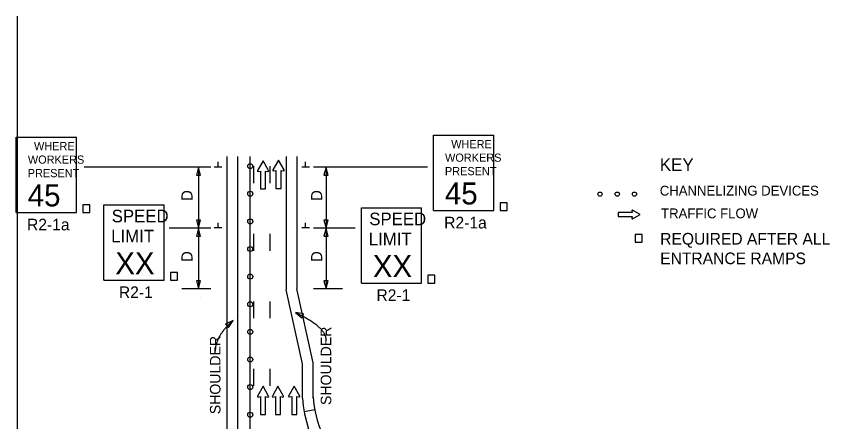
# Model space of a CAD drawing. Extents: x 16115 to 18454, y 4946 to 8326.
# Drawn here: x 16732 to 17380, y 7978 to 8301 of the extents above; entities that cross this region are included whole.
import ezdxf

# ---------------------------------------------------------------- set-up
doc = ezdxf.new("R2010")
doc.units = 0
for name, color, linetype in [('BORDER', 7, 'Continuous'), ('Level 10', 7, 'Continuous'), ('MT_SCRATCH_LEVEL_E', 7, 'Continuous'), ('PAVT_EDGE_EX', 7, 'Continuous'), ('SCRATCH_LEVEL_A', 7, 'Continuous'), ('TYPICAL_TEXT_DIMEN_EX', 7, 'Continuous')]:
    doc.layers.add(name, color=color, linetype=linetype)

msp = doc.modelspace()

# ---------------------------------------------------------------- linework, layer by layer
at = {"layer": 'BORDER'}
for p, q in [((16892.63, 8180.53), (16892.63, 8184.72)), ((16962.35, 8180.53), (16962.35, 8184.72)), ((16886.89, 8180.43), (16785.98, 8180.43)), ((16877.08, 8180.43), (16875.39, 8174.03)), ((16877.08, 8180.43), (16877.08, 8132)), ((16878.78, 8174.03), (16877.08, 8180.43)), ((16895.66, 8180.53), (16889.61, 8180.53)), ((16965.37, 8180.53), (16959.32, 8180.53)), ((17059.37, 8180.43), (16968.59, 8180.43)), ((16978.69, 8180.43), (16977, 8174.03)), ((16978.69, 8180.43), (16978.69, 8132)), ((16980.39, 8174.03), (16978.69, 8180.43)), ((16875.39, 8174.03), (16877.08, 8174.03)), ((16877.08, 8174.03), (16878.78, 8174.03)), ((16977, 8174.03), (16978.69, 8174.03)), ((16978.69, 8174.03), (16980.39, 8174.03)), ((16877.08, 8138.41), (16875.39, 8138.41)), ((16875.39, 8138.41), (16877.08, 8132)), ((16877.08, 8132), (16878.78, 8138.41)), ((16878.78, 8138.41), (16877.08, 8138.41)), ((16978.69, 8138.41), (16977, 8138.41)), ((16977, 8138.41), (16978.69, 8132)), ((16978.69, 8132), (16980.39, 8138.41)), ((16980.39, 8138.41), (16978.69, 8138.41)), ((16886.89, 8132), (16853.73, 8132)), ((16877.08, 8132), (16875.39, 8125.6)), ((16877.08, 8132), (16877.08, 8083.57)), ((16878.78, 8125.6), (16877.08, 8132)), ((16895.66, 8132.1), (16889.61, 8132.1)), ((16892.63, 8132.1), (16892.63, 8136.29)), ((16965.37, 8132.1), (16959.32, 8132.1)), ((16962.35, 8132.1), (16962.35, 8136.29)), ((17001.75, 8132), (16968.59, 8132)), ((16978.69, 8132), (16977, 8125.6)), ((16978.69, 8132), (16978.69, 8083.57)), ((16980.39, 8125.6), (16978.69, 8132)), ((16875.39, 8125.6), (16877.08, 8125.6)), ((16877.08, 8125.6), (16878.78, 8125.6)), ((16977, 8125.6), (16978.69, 8125.6)), ((16978.69, 8125.6), (16980.39, 8125.6)), ((16877.08, 8089.98), (16875.39, 8089.98)), ((16875.39, 8089.98), (16877.08, 8083.57)), ((16877.08, 8083.57), (16878.78, 8089.98)), ((16878.78, 8089.98), (16877.08, 8089.98)), ((16978.69, 8089.98), (16977, 8089.98)), ((16977, 8089.98), (16978.69, 8083.57)), ((16978.69, 8083.57), (16980.39, 8089.98)), ((16980.39, 8089.98), (16978.69, 8089.98)), ((16886.89, 8083.57), (16863.83, 8083.57)), ((16991.66, 8083.57), (16968.59, 8083.57)), ((16878.97, 8076.84), (16878.97, 8076.84)), ((16954.29, 8064.7), (16959.41, 8060.5)), ((16960.82, 8063.58), (16954.29, 8064.7)), ((16959.41, 8060.5), (16960.11, 8062.04)), ((16960.11, 8062.04), (16960.82, 8063.58)), ((16904.66, 8058.27), (16898.69, 8055.4)), ((16898.69, 8055.4), (16899.79, 8054.11)), ((16899.79, 8054.11), (16900.89, 8052.82)), ((16900.89, 8052.82), (16904.66, 8058.27)), ((16961.22, 7985.76), (16969.66, 7987.47))]:
    msp.add_line(p, q, dxfattribs=at)
msp.add_lwpolyline([(16918.32, 7255.33), (16918.32, 8189.12)], dxfattribs=at)
for centre in [(16918.32, 8181.33), (16918.32, 8159.33), (16918.32, 8137.33), (16918.32, 8115.33), (16918.32, 8093.33), (16918.32, 8071.33), (16918.32, 8049.33), (16918.32, 8027.33), (16918.32, 8005.33), (16918.32, 7983.33)]:
    msp.add_circle(centre, 2, dxfattribs=at)
for points in [[(16954.29, 8064.7), (16978.64, 8053.56), (16978.64, 8042.42)], [(16904.66, 8058.27), (16890.42, 8046.09), (16890.42, 8033.92)]]:
    msp.add_open_spline(points, degree=2, dxfattribs=at)
at = {"layer": 'Level 10'}
for p, q in [((16731.93, 8204.43), (16779.93, 8204.43)), ((16731.93, 8144.43), (16731.93, 8204.43)), ((16779.93, 8144.43), (16779.93, 8204.43)), ((17064.2, 8205.99), (17112.2, 8205.99)), ((17064.2, 8145.99), (17064.2, 8205.99)), ((17112.2, 8145.99), (17112.2, 8205.99)), ((16731.93, 8144.43), (16779.93, 8144.43)), ((16801.65, 8150.53), (16849.65, 8150.53)), ((16801.65, 8090.53), (16801.65, 8150.53)), ((16849.65, 8090.53), (16849.65, 8150.53)), ((17006.8, 8148.2), (17054.8, 8148.2)), ((17006.8, 8088.2), (17006.8, 8148.2)), ((17054.8, 8088.2), (17054.8, 8148.2)), ((17064.2, 8145.99), (17112.2, 8145.99)), ((16801.65, 8090.53), (16849.65, 8090.53)), ((17006.8, 8088.2), (17054.8, 8088.2))]:
    msp.add_line(p, q, dxfattribs=at)
for points in [[(17117.22, 8145.99), (17122.81, 8145.99), (17122.81, 8152.16), (17117.22, 8152.16)], [(16784.94, 8144.43), (16790.54, 8144.43), (16790.54, 8150.61), (16784.94, 8150.61)], [(17224.98, 8120.68), (17230.57, 8120.68), (17230.57, 8126.85), (17224.98, 8126.85)], [(16854.67, 8090.53), (16860.26, 8090.53), (16860.26, 8096.7), (16854.67, 8096.7)], [(17059.82, 8088.2), (17065.41, 8088.2), (17065.41, 8094.37), (17059.82, 8094.37)]]:
    msp.add_lwpolyline(points, close=True, dxfattribs=at)
for centre in [(17196.89, 8159.03), (17210.59, 8159.03), (17224.3, 8159.03)]:
    msp.add_circle(centre, 1.68, dxfattribs=at)
at = {"layer": 'MT_SCRATCH_LEVEL_E'}
for p, q in [((16928.48, 8185.61), (16924.06, 8177.81)), ((16932.94, 8177.81), (16928.48, 8185.61)), ((16940.76, 8186.06), (16936.34, 8178.27)), ((16945.22, 8178.27), (16940.76, 8186.06)), ((16924.58, 8177.08), (16926.49, 8177.42)), ((16926.49, 8177.42), (16926.49, 8163.15)), ((16930.52, 8163.15), (16930.52, 8177.42)), ((16930.52, 8177.42), (16932.43, 8177.08)), ((16936.85, 8177.53), (16938.77, 8177.87)), ((16938.77, 8177.87), (16938.77, 8163.6)), ((16942.79, 8163.6), (16942.79, 8177.87)), ((16942.79, 8177.87), (16944.71, 8177.53)), ((16926.49, 8163.15), (16930.52, 8163.15)), ((16938.77, 8163.6), (16942.79, 8163.6)), ((17222.53, 8144.36), (17211.38, 8144.36)), ((17211.38, 8144.36), (17211.38, 8141.22)), ((17222.53, 8144.36), (17211.38, 8144.36)), ((17211.38, 8144.36), (17211.38, 8141.22)), ((17222.26, 8145.86), (17222.53, 8144.36)), ((17222.26, 8145.86), (17222.53, 8144.36)), ((17228.93, 8142.8), (17222.84, 8146.26)), ((17228.93, 8142.8), (17222.84, 8146.26)), ((17211.38, 8141.22), (17222.53, 8141.22)), ((17211.38, 8141.22), (17222.53, 8141.22)), ((17222.53, 8141.22), (17222.26, 8139.72)), ((17222.53, 8141.22), (17222.26, 8139.72)), ((17222.84, 8139.32), (17228.93, 8142.8)), ((17222.84, 8139.32), (17228.93, 8142.8)), ((16928.48, 8005.95), (16924.06, 7998.15)), ((16932.94, 7998.15), (16928.48, 8005.95)), ((16940.3, 8005.95), (16935.88, 7998.15)), ((16944.77, 7998.15), (16940.3, 8005.95)), ((16953.31, 8005.98), (16948.88, 7998.18)), ((16957.77, 7998.18), (16953.31, 8005.98)), ((16924.58, 7997.42), (16926.49, 7997.76)), ((16926.49, 7997.76), (16926.49, 7983.49)), ((16930.52, 7983.49), (16930.52, 7997.76)), ((16930.52, 7997.76), (16932.43, 7997.42)), ((16936.4, 7997.42), (16938.31, 7997.76)), ((16938.31, 7997.76), (16938.31, 7983.49)), ((16942.34, 7983.49), (16942.34, 7997.76)), ((16942.34, 7997.76), (16944.25, 7997.42)), ((16949.4, 7997.45), (16951.32, 7997.79)), ((16951.32, 7997.79), (16951.32, 7983.52)), ((16955.34, 7983.52), (16955.34, 7997.79)), ((16955.34, 7997.79), (16957.26, 7997.45)), ((16926.49, 7983.49), (16930.52, 7983.49)), ((16938.31, 7983.49), (16942.34, 7983.49)), ((16951.32, 7983.52), (16955.34, 7983.52))]:
    msp.add_line(p, q, dxfattribs=at)
for centre, radius, start, end in [((16924.5, 8177.57), 0.498, 150.42484, 279.96381), ((16932.5, 8177.57), 0.498, 260.03619, 29.77312), ((16936.77, 8178.03), 0.498, 150.42484, 279.96381), ((16944.78, 8178.03), 0.498, 260.03619, 29.77312), ((17222.65, 8145.92), 0.389, 60.42484, 189.96381), ((17222.65, 8145.92), 0.389, 60.42484, 189.96381), ((17222.65, 8139.66), 0.389, 170.03619, 299.77312), ((17222.65, 8139.66), 0.389, 170.03619, 299.77312), ((16924.5, 7997.91), 0.498, 150.42484, 279.96381), ((16932.5, 7997.91), 0.498, 260.03619, 29.77312), ((16936.32, 7997.91), 0.498, 150.42484, 279.96381), ((16944.33, 7997.91), 0.498, 260.03619, 29.77312), ((16949.32, 7997.94), 0.498, 150.42484, 279.96381), ((16957.33, 7997.94), 0.498, 260.03619, 29.77312)]:
    msp.add_arc(centre, radius, start, end, dxfattribs=at)
at = {"layer": 'PAVT_EDGE_EX'}
for p, q in [((16899.59, 8189.12), (16899.59, 7796.21)), ((16908.2, 8189.12), (16908.2, 7796.21)), ((16946.95, 8189.12), (16946.95, 8082.7)), ((16955.51, 8189.12), (16955.51, 8083.57)), ((16959.83, 8023.77), (16946.95, 8082.7)), ((16968.39, 8024.65), (16955.51, 8083.57)), ((16959.83, 7996.6), (16959.83, 8023.77)), ((16968.41, 7996.6), (16968.41, 8024.65))]:
    msp.add_line(p, q, dxfattribs=at)
for radius in [100.47, 91.87]:
    msp.add_arc((17060.03, 8003.94), radius, 184.18699, 241.32804, dxfattribs=at)
at = {"layer": 'SCRATCH_LEVEL_A'}
for p, q in [((16732.78, 7648.38), (16732.78, 8300.7)), ((16959.83, 8023.77), (16959.83, 8023.77))]:
    msp.add_line(p, q, dxfattribs=at)
for points in [[(16921.12, 8167.77), (16921.12, 8181.22)], [(16934.03, 8167.77), (16934.03, 8181.22)], [(16921.12, 8113.96), (16921.12, 8127.41)], [(16934.03, 8113.96), (16934.03, 8127.41)], [(16921.12, 8060.14), (16921.12, 8073.6)], [(16934.03, 8060.14), (16934.03, 8073.6)], [(16921.12, 8006.33), (16921.12, 8019.78)], [(16934.03, 8006.33), (16934.03, 8019.78)]]:
    msp.add_lwpolyline(points, dxfattribs=at)

# ---------------------------------------------------------------- texts
at = {"layer": 'BORDER'}
for s, height, p in [('D', 8.83, (16872.3, 8153.7)), ('D', 8.83, (16975.58, 8153.7)), ('D', 8.83, (16872.3, 8105.05)), ('D', 8.83, (16975.58, 8105.05)), ('SHOULDER', 8.4, (16982.78, 7991.05)), ('SHOULDER', 8.4, (16894.58, 7983.69))]:
    msp.add_text(s, height=height, rotation=90, dxfattribs=at).set_placement(p)
at = {"layer": 'Level 10'}
for s, height, p in [('WHERE', 6.5, (16746.06, 8194.04)), ('WHERE', 6.5, (17078.34, 8195.59)), ('WORKERS', 6.5, (16741.16, 8183.29)), ('WORKERS', 6.5, (17073.43, 8184.84)), ('PRESENT', 6.5, (16741.07, 8172.54)), ('PRESENT', 6.5, (17073.34, 8174.09)), ('45', 17.538, (16741.06, 8149.25)), ('45', 17.538, (17073.33, 8150.8)), ('SPEED', 10, (16807.94, 8136.61)), ('SPEED', 10, (17013.09, 8134.28)), ('R2-1a', 9.3, (16740.49, 8130.13)), ('R2-1a', 9.3, (17072.77, 8131.69)), ('LIMIT', 10, (16807.53, 8120.61)), ('LIMIT', 10, (17012.68, 8118.28)), ('XX', 17.538, (16810.78, 8095.23)), ('XX', 17.538, (17015.94, 8092.9)), ('R2-1', 9.3, (16813.66, 8076.23)), ('R2-1', 9.3, (17018.81, 8073.9))]:
    msp.add_text(s, height=height, dxfattribs=at).set_placement(p)
at = {"layer": 'TYPICAL_TEXT_DIMEN_EX'}
for s, height, p in [('KEY', 10.09, (17244.48, 8177.53)), ('CHANNELIZING DEVICES', 7.8196, (17244.48, 8157.88)), ('TRAFFIC FLOW', 7.8196, (17245.51, 8139.8)), ('REQUIRED AFTER ALL', 9.3, (17244.8, 8118.82)), ('ENTRANCE RAMPS', 9.3, (17244.8, 8103.22))]:
    msp.add_text(s, height=height, dxfattribs=at).set_placement(p)

doc.saveas('drawing.dxf')
